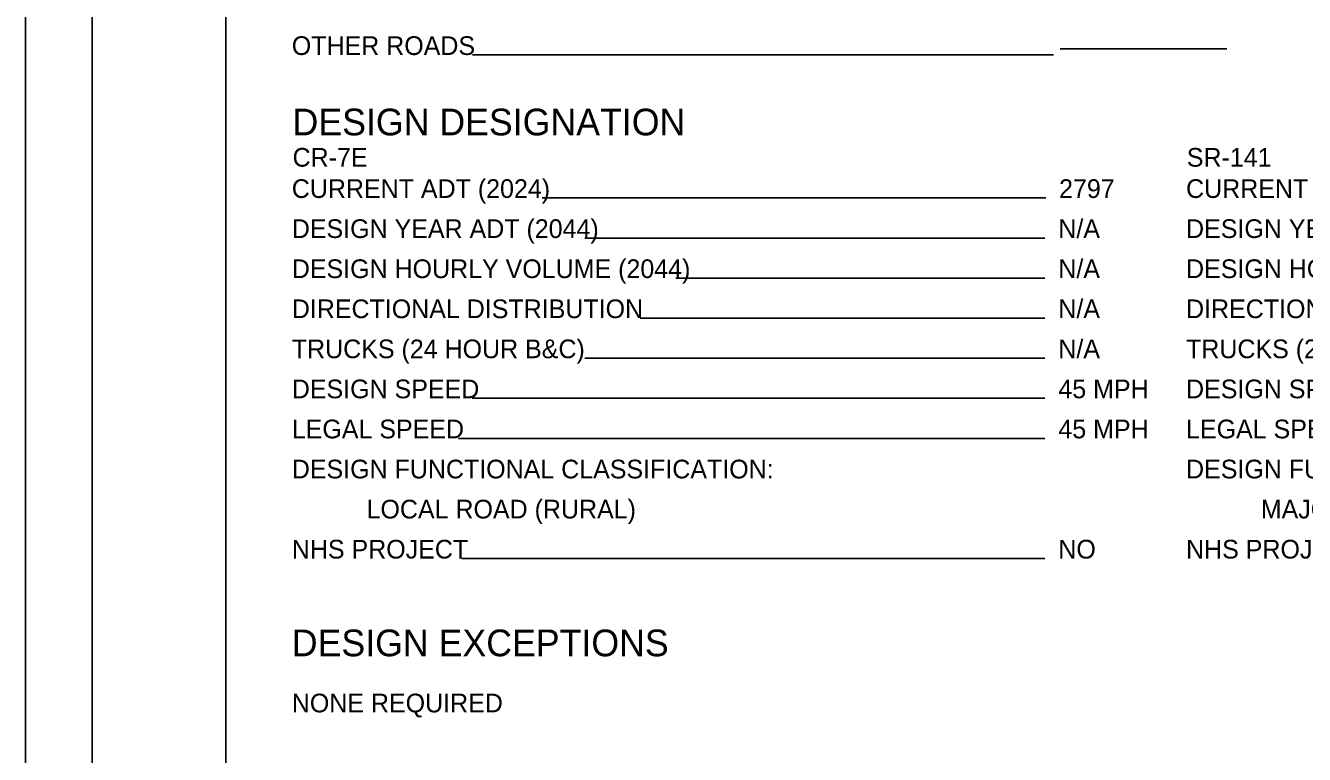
# Model space of a CAD drawing. Extents: x 0 to 34, y 0 to 22.
# Drawn here: x 0 to 9.58, y 5.64 to 11.1 of the extents above; entities that cross this region are included whole.
import ezdxf

# ---------------------------------------------------------------- set-up
doc = ezdxf.new("R2010")
doc.units = 0
for name, color, linetype in [('SH_Border', 7, 'Continuous'), ('SH_Data', 7, 'Continuous'), ('SH_Text', 7, 'Continuous')]:
    doc.layers.add(name, color=color, linetype=linetype)

msp = doc.modelspace()

# ---------------------------------------------------------------- linework, layer by layer
at = {"layer": 'SH_Border'}
for points in [[(0.5, 21.5), (1.5, 21.5), (1.5, 0.5), (0.5, 0.5)], [(1.5, 21.5), (33.5, 21.5), (33.5, 0.5), (1.5, 0.5)]]:
    msp.add_lwpolyline(points, close=True, dxfattribs=at)
at = {"layer": 'SH_Data'}
for p, q in [((9, 10.9223), (7.75, 10.9223)), ((7.7, 10.8767), (3.3471, 10.8767)), ((7.6424, 9.8062), (3.871, 9.8062)), ((7.6368, 9.5062), (4.1885, 9.5062)), ((7.6368, 9.2062), (4.8723, 9.2062)), ((7.6368, 8.9062), (4.6037, 8.9062)), ((7.6368, 8.6062), (4.1885, 8.6062)), ((7.6368, 8.3062), (3.346, 8.3062)), ((7.6368, 8.0062), (3.2422, 8.0062)), ((7.6368, 7.1062), (3.2669, 7.1062))]:
    msp.add_line(p, q, dxfattribs=at)
msp.add_lwpolyline([(0, 0), (34, 0), (34, 22), (0, 22)], close=True, dxfattribs=at)

# ---------------------------------------------------------------- texts
msp.add_text('DESIGN DESIGNATION', height=0.2, dxfattribs=at).set_placement((2, 10.2747))
at = {"layer": 'SH_Text'}
for s, height, p in [('OTHER ROADS', 0.14, (1.9944, 10.8767)), ('CR-7E', 0.14, (2, 10.0404)), ('SR-141', 0.14, (8.6991, 10.0404)), ('CURRENT ADT (2024)', 0.14, (1.9944, 9.8062)), ('2797', 0.14, (7.7424, 9.8062)), ('CURRENT ADT (2024)', 0.14, (8.6935, 9.8062)), ('DESIGN YEAR ADT (2044)', 0.14, (1.9944, 9.5062)), ('N/A', 0.14, (7.7368, 9.5062)), ('DESIGN YEAR ADT (2044)', 0.14, (8.6935, 9.5062)), ('DESIGN HOURLY VOLUME (2044)', 0.14, (1.9944, 9.2062)), ('N/A', 0.14, (7.7368, 9.2062)), ('DESIGN HOURLY VOLUME (2044)', 0.14, (8.6935, 9.2062)), ('DIRECTIONAL DISTRIBUTION', 0.14, (1.9944, 8.9062)), ('N/A', 0.14, (7.7368, 8.9062)), ('DIRECTIONAL DISTRIBUTION', 0.14, (8.6935, 8.9062)), ('TRUCKS (24 HOUR B&C)', 0.14, (1.9944, 8.6062)), ('N/A', 0.14, (7.7368, 8.6062)), ('TRUCKS (24 HOUR B&C)', 0.14, (8.6935, 8.6062)), ('DESIGN SPEED', 0.14, (1.9944, 8.3062)), ('45 MPH', 0.14, (7.7368, 8.3062)), ('DESIGN SPEED', 0.14, (8.6935, 8.3062)), ('LEGAL SPEED', 0.14, (1.9944, 8.0062)), ('45 MPH', 0.14, (7.7368, 8.0062)), ('LEGAL SPEED', 0.14, (8.6935, 8.0062)), ('DESIGN FUNCTIONAL CLASSIFICATION:', 0.14, (1.9944, 7.7062)), ('DESIGN FUNCTIONAL CLASSIFICATION:', 0.14, (8.6935, 7.7062)), ('LOCAL ROAD (RURAL)', 0.14, (2.5544, 7.4062)), ('MAJOR COLLECTOR (RURAL)', 0.14, (9.2535, 7.4062)), ('NHS PROJECT', 0.14, (1.9944, 7.1062)), ('NO', 0.14, (7.7368, 7.1062)), ('NHS PROJECT', 0.14, (8.6935, 7.1062)), ('DESIGN EXCEPTIONS', 0.2, (1.9944, 6.3744)), ('NONE REQUIRED', 0.14, (1.9944, 5.9544))]:
    msp.add_text(s, height=height, dxfattribs=at).set_placement(p)

doc.saveas('drawing.dxf')
